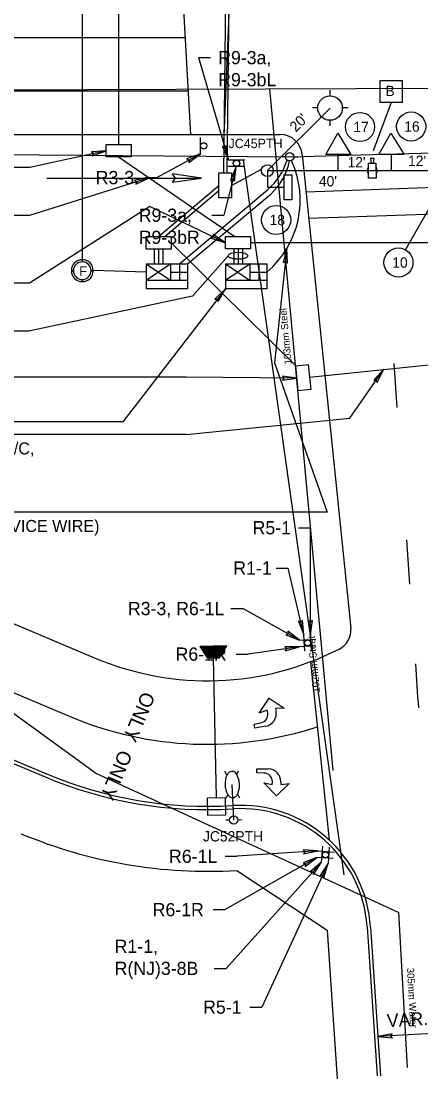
# Model space of a CAD drawing. Extents: x 488740 to 507913, y 466518 to 497949.
# Drawn here: x 503408.4 to 503498.7, y 495805.8 to 496045.1 of the extents above; entities that cross this region are included whole.
import ezdxf

# ---------------------------------------------------------------- set-up
doc = ezdxf.new("R2010")
doc.units = 0
for name, color, linetype in [('1', 7, 'Continuous'), ('10', 7, 'Continuous'), ('12', 7, 'Continuous'), ('23', 7, 'Continuous'), ('32', 7, 'Continuous'), ('36', 7, 'Continuous'), ('38', 7, 'Continuous'), ('42', 7, 'Continuous'), ('6', 7, 'Continuous'), ('8', 7, 'Continuous')]:
    doc.layers.add(name, color=color, linetype=linetype)

msp = doc.modelspace()

# ---------------------------------------------------------------- linework, layer by layer
at = {"layer": '1'}
for p, q in [((503325.93, 496019.46), (503467, 496019.46)), ((503468.17, 496014.44), (503467.3, 496014.44)), ((503470.04, 496014.44), (503470.95, 496014.44)), ((503471.88, 496014.92), (503482.9, 495907.73)), ((503126.85, 495994.96), (503413.81, 495874.09)), ((503127.14, 495995.66), (503414.1, 495874.78)), ((503268.83, 495966.81), (503425.13, 495900.97)), ((503454.91, 495874.46), (503454.43, 495875.35)), ((503457.09, 495874.6), (503457.49, 495875.48)), ((503456.43, 495864.35), (503456.11, 495872.35)), ((503455.11, 495870.12), (503454.67, 495869.22)), ((503457.26, 495870.21), (503457.74, 495869.34)), ((503455.53, 495864.31), (503454.66, 495864.27)), ((503457.4, 495864.38), (503458.3, 495864.42)), ((503457.13, 495852.93), (503477.59, 495839.42)), ((503477.59, 495839.42), (503479.82, 495805.75)), ((503486.61, 495840.19), (503488.84, 495806.41)), ((503487.37, 495840.06), (503489.59, 495806.46))]:
    msp.add_line(p, q, dxfattribs=at)
msp.add_lwpolyline([(503450.56, 495865.36), (503450.48, 495869.36), (503454.48, 495869.44), (503454.56, 495865.44)], close=True, dxfattribs=at)
for centre in [(503469.08, 496014.43), (503456.44, 495864.33)]:
    msp.add_circle(centre, 0.939, dxfattribs=at)
for centre, radius, start, end in [((503467, 496014.56), 4.9, 4.1335, 90), ((503478.02, 495907.38), 4.9, 297.1014, 4.1335), ((503450.49, 495961.17), 65.32, 247.1579, 297.1014), ((503450.49, 495961.17), 93.74, 247.1579, 273.51), ((503450.49, 495961.17), 94.49, 247.1579, 273.51), ((503458.03, 495838.26), 29.39, 3.51, 93.51), ((503458.03, 495838.26), 28.64, 3.8622, 93.51), ((503450.49, 495961.16), 108.43, 247.1579, 273.51)]:
    msp.add_arc(centre, radius, start, end, dxfattribs=at)
msp.add_ellipse((503456.11, 495872.35), major_axis=(0.12, -3.07), ratio=0.504, dxfattribs=at)
at = {"layer": '10'}
for p, q in [((503414.23, 496009.62), (503449.13, 496009.62)), ((503482.68, 495955.31), (503490.36, 495966.33)), ((503445.69, 495964.56), (503317.07, 495964.56)), ((503470.74, 495964.29), (503445.69, 495964.56)), ((503445.69, 495951.56), (503482.68, 495955.31)), ((503445.69, 495951.56), (503317.07, 495951.56))]:
    msp.add_line(p, q, dxfattribs=at)
for points in [[(503449.13, 496009.62), (503442.51, 496010.57), (503443.22, 496009.62), (503442.51, 496008.68)], [(503490.36, 495966.33), (503488.08, 495963.88), (503488.67, 495963.91), (503488.86, 495963.34)], [(503470.74, 495964.29), (503467.44, 495964.8), (503467.79, 495964.33), (503467.43, 495963.86)]]:
    msp.add_lwpolyline(points, close=True, dxfattribs=at)
at = {"layer": '12'}
for p, q in [((503427.6, 496015.8), (503410.38, 496012.02)), ((503410.38, 496012.02), (503281.76, 496012.02)), ((503437.34, 496009.65), (503410.26, 496001.15)), ((503410.26, 496001.15), (503281.64, 496001.15)), ((503468.48, 495993.71), (503465.65, 495967.79)), ((503410.26, 495985.8), (503281.64, 495985.8)), ((503454.56, 495984.57), (503431.34, 495954.47)), ((503410.15, 495974.93), (503281.52, 495974.93)), ((503465.65, 495967.79), (503477.57, 495934.01)), ((503431.34, 495954.47), (503302.72, 495954.47)), ((503477.57, 495934.01), (503348.94, 495934.01))]:
    msp.add_line(p, q, dxfattribs=at)
for points in [[(503427.6, 496015.8), (503424.27, 496015.55), (503424.72, 496015.17), (503424.47, 496014.63)], [(503437.34, 496009.65), (503434.04, 496009.11), (503434.52, 496008.76), (503434.33, 496008.21)], [(503454.56, 495994.99), (503451.78, 495996.84), (503451.9, 495996.26), (503451.37, 495995.99)], [(503468.48, 495993.71), (503467.65, 495990.48), (503468.16, 495990.78), (503468.59, 495990.38)], [(503454.56, 495984.57), (503452.17, 495982.24), (503452.76, 495982.24), (503452.91, 495981.67)]]:
    msp.add_lwpolyline(points, close=True, dxfattribs=at)
for points in [[(503454.56, 495994.99), (503437.45, 496003.17), (503410.26, 495985.8)], [(503455.19, 495992.02), (503447.1, 495982.9), (503410.15, 495974.93)]]:
    msp.add_lwpolyline(points, dxfattribs=at)
msp.add_ellipse((503457.42, 495992.02), major_axis=(-2.23, 0), ratio=0.356808, dxfattribs=at)
at = {"layer": '23'}
for p, q in [((503462.78, 496220.08), (503454.1, 496017.3)), ((503346.41, 496029.35), (503748.62, 496030.81)), ((503478.95, 495875.52), (503464.57, 496029.78)), ((503469.08, 496014.43), (503748.62, 496022.1)), ((503234.58, 496016.17), (503469.08, 496014.43)), ((503481.44, 495851.92), (503458.62, 496013.71)), ((503448.82, 495903.56), (503454.81, 495903.68)), ((503448.87, 495903.49), (503454.77, 495903.61)), ((503448.91, 495903.43), (503454.73, 495903.55)), ((503448.95, 495903.36), (503454.69, 495903.48)), ((503449, 495903.29), (503454.65, 495903.41)), ((503449.04, 495903.23), (503454.61, 495903.34)), ((503449.09, 495903.16), (503454.57, 495903.27)), ((503449.13, 495903.09), (503454.53, 495903.2)), ((503449.17, 495903.03), (503454.49, 495903.14)), ((503449.22, 495902.96), (503454.45, 495903.07)), ((503449.26, 495902.89), (503454.41, 495903)), ((503449.3, 495902.83), (503454.37, 495902.93)), ((503449.35, 495902.76), (503454.33, 495902.86)), ((503449.39, 495902.69), (503454.28, 495902.79)), ((503449.43, 495902.63), (503454.24, 495902.72)), ((503449.48, 495902.56), (503454.2, 495902.66)), ((503449.52, 495902.49), (503454.16, 495902.59)), ((503449.56, 495902.43), (503454.12, 495902.52)), ((503449.61, 495902.36), (503454.08, 495902.45)), ((503449.65, 495902.29), (503454.04, 495902.38)), ((503449.7, 495902.23), (503454, 495902.31)), ((503449.74, 495902.16), (503453.96, 495902.25)), ((503449.78, 495902.09), (503453.92, 495902.18)), ((503449.83, 495902.03), (503453.88, 495902.11)), ((503449.87, 495901.96), (503453.84, 495902.04)), ((503449.91, 495901.89), (503453.79, 495901.97)), ((503449.96, 495901.83), (503453.75, 495901.9)), ((503450, 495901.76), (503453.71, 495901.84)), ((503450.04, 495901.69), (503453.67, 495901.77)), ((503450.09, 495901.63), (503453.63, 495901.7)), ((503450.13, 495901.56), (503453.59, 495901.63)), ((503450.17, 495901.49), (503453.55, 495901.56)), ((503450.22, 495901.43), (503453.51, 495901.49)), ((503450.26, 495901.36), (503453.47, 495901.43)), ((503450.31, 495901.29), (503453.43, 495901.36)), ((503450.35, 495901.23), (503453.39, 495901.29)), ((503450.39, 495901.16), (503453.35, 495901.22)), ((503450.44, 495901.09), (503453.31, 495901.15)), ((503450.48, 495901.03), (503453.26, 495901.08)), ((503452.52, 495869.4), (503451.87, 495900.99)), ((503451.87, 495900.99), (503451.87, 495900.99)), ((503393.56, 495897.96), (503425.43, 495874.84)), ((503425.43, 495874.84), (503493.76, 495843.43)), ((503495.75, 495808.31), (503493.76, 495843.43))]:
    msp.add_line(p, q, dxfattribs=at)
msp.add_lwpolyline([(503450.52, 495900.96), (503453.22, 495901.02), (503454.86, 495903.75), (503448.78, 495903.63)], close=True, dxfattribs=at)
at = {"layer": '32'}
for p, q in [((503480.07, 496011.3), (503480.07, 496014.96)), ((503492.09, 496011.3), (503492.09, 496014.96)), ((503464.05, 496011.3), (503504.11, 496011.3)), ((503464.05, 496011.3), (503464.05, 496007.55)), ((503464.05, 496007.55), (503467.83, 496007.55)), ((503495.29, 495993.35), (503501.81, 496004.81))]:
    msp.add_line(p, q, dxfattribs=at)
for points in [[(503477.24, 496014.96), (503479.95, 496019.8), (503482.91, 496014.96)], [(503489.26, 496014.96), (503491.97, 496019.8), (503494.93, 496014.96)], [(503467.83, 496010.38), (503469.6, 496010.38), (503469.6, 496004.71), (503467.83, 496004.71)]]:
    msp.add_lwpolyline(points, close=True, dxfattribs=at)
for centre, radius in [((503484.99, 496021.18), 3.29), ((503496.55, 496021.28), 3.29), ((503464.05, 496011.3), 1.34), ((503466.03, 496000.13), 3.29), ((503493.67, 495990.5), 3.29)]:
    msp.add_circle(centre, radius, dxfattribs=at)
at = {"layer": '36'}
for p, q in [((503446.71, 496019.46), (503443.98, 496069.39)), ((503395.9, 496041.4), (503445.51, 496041.4)), ((503326.93, 496029.38), (503446.17, 496029.38)), ((503581.59, 496010.27), (503472.76, 496006.44)), ((503581.68, 496004.26), (503473.37, 496000.44)), ((503493.4, 495957.69), (503492.67, 495967.68)), ((503496.28, 495917.73), (503495.56, 495927.72)), ((503380.27, 495904.25), (503419.65, 495887.66)), ((503473.83, 495900.16), (503477.98, 495859.85)), ((503462.17, 495888.54), (503464.45, 495891.92)), ((503464.45, 495891.92), (503467.83, 495889.64)), ((503464, 495889.22), (503462.17, 495888.54)), ((503464.12, 495888.59), (503464, 495889.22)), ((503467.83, 495889.64), (503465.88, 495889.58)), ((503465.88, 495889.58), (503466.01, 495888.95)), ((503461.03, 495886.03), (503462.6, 495886.33)), ((503461.21, 495885.08), (503461.03, 495886.03)), ((503463.73, 495885.57), (503461.21, 495885.08)), ((503461.67, 495874.99), (503461.69, 495875.95)), ((503463.28, 495874.96), (503461.67, 495874.99)), ((503461.69, 495875.95), (503464.25, 495875.91)), ((503466.08, 495869.79), (503463.24, 495872.72)), ((503463.24, 495872.72), (503465.16, 495872.37)), ((503465.16, 495872.37), (503465.17, 495873.01)), ((503469.01, 495872.63), (503466.08, 495869.79)), ((503467.09, 495872.98), (503467.08, 495872.34)), ((503467.08, 495872.34), (503469.01, 495872.63))]:
    msp.add_line(p, q, dxfattribs=at)
for centre, radius, start, end in [((503463.07, 496039.06), 48.52, 0.3384, 83.5869), ((496341.87, 495401.78), 7173, 3.900289, 3.980294), ((503463.18, 495888.4), 2.88, 280.9995, 10.9995), ((503450.49, 495961.17), 79.71, 247.2422, 288.1704), ((503462.23, 495888.22), 1.92, 280.9995, 10.9995), ((503463.25, 495873.04), 1.92, 359.0902, 89.0902), ((503464.21, 495873.02), 2.88, 359.0902, 89.0902)]:
    msp.add_arc(centre, radius, start, end, dxfattribs=at)
at = {"layer": '38'}
msp.add_line((503502.89, 495816.12), (503489, 495815.31), dxfattribs=at)
msp.add_lwpolyline([(503489, 495815.31), (503492.33, 495815.03), (503491.95, 495815.48), (503492.28, 495815.97)], close=True, dxfattribs=at)
at = {"layer": '42'}
for p, q in [((503448.45, 496036.87), (503455.29, 496013.7)), ((503448.45, 496036.87), (503451.16, 496036.87)), ((503448.93, 496015.12), (503448.93, 496018.79)), ((503439.07, 496009.73), (503448.93, 496015.12)), ((503455.29, 496013.7), (503458.95, 496013.7)), ((503457, 496012.22), (503454.21, 496001.2)), ((503458.84, 496012.22), (503455.18, 496012.22)), ((503436.36, 496009.73), (503439.07, 496009.73)), ((503451.5, 496001.2), (503454.21, 496001.2)), ((503471.06, 495930.47), (503473.77, 495930.47)), ((503473.78, 495906.21), (503473.77, 495930.47)), ((503466, 495921.34), (503468.71, 495921.34)), ((503472.29, 495906.24), (503468.71, 495921.34)), ((503455.76, 495912.18), (503458.47, 495912.18)), ((503471.33, 495905.04), (503458.47, 495912.18)), ((503472.5, 495902.58), (503472.29, 495906.24)), ((503473.78, 495906.21), (503473.98, 495902.56)), ((503471.31, 495903.56), (503459.71, 495901.87)), ((503474.94, 495903.77), (503471.29, 495903.56)), ((503471.33, 495905.04), (503474.99, 495905.25)), ((503457, 495901.87), (503459.71, 495901.87)), ((503476.31, 495854.74), (503476.56, 495858.4)), ((503478.03, 495858.19), (503477.78, 495854.53)), ((503475.25, 495855.87), (503454.5, 495844.05)), ((503454.54, 495856.12), (503457.25, 495856.12)), ((503475.46, 495857.33), (503457.25, 495856.12)), ((503478.9, 495855.62), (503475.25, 495855.87)), ((503475.46, 495857.33), (503479.11, 495857.08)), ((503476.31, 495854.76), (503454.7, 495830.75)), ((503477.78, 495854.55), (503462.8, 495821.98)), ((503451.79, 495844.05), (503454.5, 495844.05)), ((503451.99, 495830.75), (503454.7, 495830.75)), ((503460.09, 495821.98), (503462.8, 495821.98))]:
    msp.add_line(p, q, dxfattribs=at)
for points in [[(503455.29, 496013.7), (503454.8, 496017.01), (503454.45, 496016.53), (503453.9, 496016.74)], [(503448.93, 496015.12), (503445.8, 496013.95), (503446.34, 496013.71), (503446.26, 496013.12)], [(503457, 496012.22), (503455.73, 496009.13), (503456.28, 496009.36), (503456.65, 496008.9)], [(503472.29, 495906.24), (503471.99, 495909.56), (503471.61, 495909.11), (503471.07, 495909.34)], [(503473.78, 495906.21), (503474.25, 495909.52), (503473.78, 495909.16), (503473.3, 495909.52)], [(503471.33, 495905.04), (503468.67, 495907.06), (503468.75, 495906.48), (503468.21, 495906.23)], [(503471.31, 495903.56), (503467.97, 495903.55), (503468.39, 495903.14), (503468.1, 495902.62)], [(503475.46, 495857.33), (503472.13, 495857.58), (503472.51, 495857.14), (503472.19, 495856.64)], [(503475.25, 495855.87), (503472.14, 495854.64), (503472.69, 495854.41), (503472.61, 495853.82)], [(503476.31, 495854.76), (503473.75, 495852.62), (503474.34, 495852.57), (503474.45, 495851.99)], [(503477.78, 495854.55), (503475.97, 495851.75), (503476.55, 495851.87), (503476.83, 495851.35)]]:
    msp.add_lwpolyline(points, close=True, dxfattribs=at)
for centre in [(503449.64, 496016.9), (503457.06, 496012.99), (503457.07, 496012.93), (503473.11, 495904.39), (503473.14, 495904.37), (503473.14, 495904.44), (503473.17, 495904.4), (503477.14, 495856.46), (503477.18, 495856.51), (503477.19, 495856.44), (503477.2, 495856.47)]:
    msp.add_circle(centre, 0.721, dxfattribs=at)
at = {"layer": '6'}
for p, q in [((503454.17, 496010.78), (503455.93, 496157.27)), ((503454.95, 496010.78), (503456.7, 496157)), ((503422.21, 496136.17), (503422.21, 495991.12)), ((503430.39, 496136.05), (503430.43, 496017.22)), ((503489.52, 496026.7), (503489.52, 496031.66)), ((503489.52, 496031.66), (503494.48, 496031.66)), ((503494.48, 496031.66), (503494.48, 496026.7)), ((503492, 496026.7), (503487.99, 496015.75)), ((503494.48, 496026.7), (503489.52, 496026.7)), ((503430.43, 496014.38), (503456.68, 495996.41)), ((503455.96, 496007.95), (503462.74, 496011.61)), ((503486.93, 496010.56), (503486.9, 496012.06)), ((503488.6, 496012.09), (503488.62, 496010.59)), ((503439.46, 495996.39), (503453.11, 496007.95)), ((503440.85, 495996.39), (503453.11, 496006.77)), ((503444.16, 495990.17), (503464.11, 496006.98)), ((503446, 495990.17), (503464.88, 496006.08)), ((503442.29, 495994.96), (503470.45, 495967.11)), ((503460.23, 495995), (503577.07, 495995)), ((503438.49, 495993.54), (503438.49, 495990.17)), ((503439.46, 495993.54), (503439.46, 495990.17)), ((503440.45, 495993.54), (503440.45, 495990.17)), ((503456.47, 495993.57), (503456.47, 495990.2)), ((503457.43, 495993.57), (503457.43, 495990.2)), ((503458.43, 495993.57), (503458.43, 495990.2)), ((503422.21, 495991.12), (503422.21, 495990.65)), ((503422.21, 495991.12), (503422.21, 495990.65)), ((503436.63, 495990.17), (503442.25, 495986.42)), ((503442.25, 495990.17), (503436.63, 495986.42)), ((503436.63, 495990.17), (503446, 495990.17)), ((503436.63, 495990.17), (503436.63, 495986.42)), ((503442.25, 495986.42), (503442.25, 495990.17)), ((503444.16, 495990.17), (503444.16, 495986.42)), ((503446, 495990.17), (503446, 495986.42)), ((503454.56, 495990.2), (503460.18, 495986.45)), ((503460.18, 495990.2), (503454.56, 495986.45)), ((503454.56, 495990.2), (503463.93, 495990.2)), ((503454.56, 495990.2), (503454.56, 495986.45)), ((503460.18, 495986.45), (503460.18, 495990.2)), ((503462.1, 495990.2), (503462.1, 495986.45)), ((503463.93, 495990.2), (503463.93, 495986.45)), ((503419.75, 495988.65), (503420.22, 495988.65)), ((503420.22, 495988.65), (503419.75, 495988.65)), ((503424.21, 495988.65), (503424.68, 495988.65)), ((503424.68, 495988.65), (503424.21, 495988.65)), ((503436.63, 495988.3), (503424.7, 495988.67)), ((503442.25, 495988.3), (503446, 495988.3)), ((503460.18, 495988.32), (503463.93, 495988.32)), ((503422.21, 495986.65), (503422.21, 495986.18)), ((503422.21, 495986.65), (503422.21, 495986.18)), ((503446, 495986.42), (503436.63, 495986.42)), ((503436.63, 495986.42), (503436.63, 495984.55)), ((503446, 495984.55), (503436.63, 495984.55)), ((503446, 495986.42), (503446, 495984.55)), ((503463.93, 495986.45), (503454.56, 495986.45)), ((503454.56, 495986.45), (503454.56, 495984.57)), ((503463.93, 495984.57), (503454.56, 495984.57)), ((503463.93, 495986.45), (503463.93, 495984.57)), ((503473.57, 495964.59), (503570.19, 495974.61))]:
    msp.add_line(p, q, dxfattribs=at)
for points in [[(503427.6, 496017.22), (503433.27, 496017.22), (503433.27, 496014.39), (503427.6, 496014.39)], [(503488.02, 496013), (503488.15, 496014.07), (503487.32, 496014.05), (503487.49, 496012.99)], [(503453.11, 496005.11), (503453.11, 496010.78), (503455.95, 496010.78), (503455.95, 496005.11)], [(503488.59, 496013.01), (503488.65, 496009.61), (503486.94, 496009.58), (503486.88, 496012.98)], [(503436.63, 495996.39), (503442.3, 495996.39), (503442.3, 495993.55), (503436.63, 495993.55)], [(503454.56, 495996.41), (503460.23, 495996.41), (503460.23, 495993.58), (503454.56, 495993.58)], [(503470.45, 495967.11), (503473.28, 495967.4), (503473.86, 495961.77), (503471.03, 495961.48)]]:
    msp.add_lwpolyline(points, close=True, dxfattribs=at)
for centre, radius, start, end in [((503450.09, 496004.62), 21.38, 310.3663, 24.7939), ((503454.56, 496018.04), 14.61, 310.8103, 342.6393), ((503455.68, 496016.12), 13.62, 312.4616, 348.8434), ((503487.76, 496011.33), 1.13, 139.5759, 222.3955), ((503487.76, 496011.33), 1.13, 319.5761, 42.394), ((503422.21, 495988.65), 2.47, 90, 180), ((503422.21, 495988.65), 2, 90, 180), ((503422.21, 495988.65), 2.47, 0, 90), ((503422.21, 495988.65), 2, 0, 90), ((503422.21, 495988.65), 2.47, 180, 270), ((503422.21, 495988.65), 2, 180, 270), ((503422.21, 495988.65), 2.47, 270, 0), ((503422.21, 495988.65), 2, 270, 0)]:
    msp.add_arc(centre, radius, start, end, dxfattribs=at)
at = {"layer": '8'}
for p, q in [((503478.19, 496029.47), (503478.19, 496028.24)), ((503464.05, 496011.3), (503478.21, 496025.46)), ((503475.43, 496025.49), (503474.28, 496025.49)), ((503482.32, 496025.49), (503480.99, 496025.49)), ((503478.19, 496022.68), (503478.19, 496021.45))]:
    msp.add_line(p, q, dxfattribs=at)
msp.add_circle((503478.21, 496025.46), 2.78, dxfattribs=at)

# ---------------------------------------------------------------- texts
at = {"layer": '1'}
for s, height, p in [('JC45PTH', 2.109, (503455.26, 496016.39)), ('JC52PTH', 2.344, (503449.49, 495859.47))]:
    msp.add_text(s, height=height, dxfattribs=at).set_placement(p)
at = {"layer": '10'}
msp.add_text('A-10/C, B-10/C, C-5/C, D-5/C, E-2/C,    ', height=2.7163, dxfattribs=at).set_placement((503351.44, 495947.07))
at = {"layer": '12'}
msp.add_text('3-1/C#2 (SERVICE WIRE)                         ', height=2.7163, dxfattribs=at).set_placement((503383.31, 495929.52))
at = {"layer": '23'}
for s, height, rotation, p in [('103mm Steel', 1.6204, 95.3255, (503469.54, 495967.52)), ('102mm Steet', 1.6205, 95.1971, (503475.93, 495893.23)), ('305mm Water', 1.6204, 273.2441, (503495.57, 495830.84))]:
    msp.add_text(s, height=height, rotation=rotation, dxfattribs=at).set_placement(p)
at = {"layer": '32'}
msp.add_text("20'", height=2.344, rotation=45.0002, dxfattribs=at).set_placement((503470.49, 496019.89))
for s, p in [('17', (503483.49, 496020.01)), ('16', (503494.99, 496020.11)), ("12'", (503482.17, 496012.02)), ("12'", (503495.85, 496012.35)), ("40'", (503475.69, 496007.71)), ('18', (503464.54, 495998.96)), ('10', (503492.27, 495989.32))]:
    msp.add_text(s, height=2.344, dxfattribs=at).set_placement(p)
at = {"layer": '36'}
for p in [(503435.84, 495893.62), (503430.68, 495880.43)]:
    msp.add_text('ONLY', height=3.193, rotation=247.1557, dxfattribs=at).set_placement(p)
at = {"layer": '38'}
msp.add_text('VAR.', height=2.993, rotation=3.3115, dxfattribs=at).set_placement((503491.13, 495817.43))
at = {"layer": '42'}
for s, height, p in [('R9-3a,', 2.993, (503452.93, 496035.37)), ('R9-3bL', 2.993, (503452.93, 496030.38)), ('R3-3', 2.993, (503425.24, 496008.23)), ('R9-3a,', 2.993, (503434.97, 495999.7)), ('R9-3bR', 2.993, (503434.97, 495994.71)), ('R5-1', 2.993, (503460.71, 495928.98)), ('R1-1', 2.993, (503456.35, 495919.85)), ('R3-3, R6-1L', 2.9928, (503432.53, 495910.69)), ('R6-1R', 2.993, (503443.3, 495900.38)), ('R6-1L', 2.993, (503441.82, 495854.62)), ('R6-1R', 2.993, (503438.12, 495842.55)), ('R1-1,', 2.993, (503429.53, 495834.25)), ('R(NJ)3-8B', 2.993, (503429.53, 495829.26)), ('R5-1', 2.993, (503449.52, 495820.49))]:
    msp.add_text(s, height=height, dxfattribs=at).set_placement(p)
at = {"layer": '6'}
for s, height, p in [('B', 2.34, (503490.73, 496028.15)), ('F', 2.2, (503421.5, 495987.47))]:
    msp.add_text(s, height=height, dxfattribs=at).set_placement(p)

doc.saveas('drawing.dxf')
